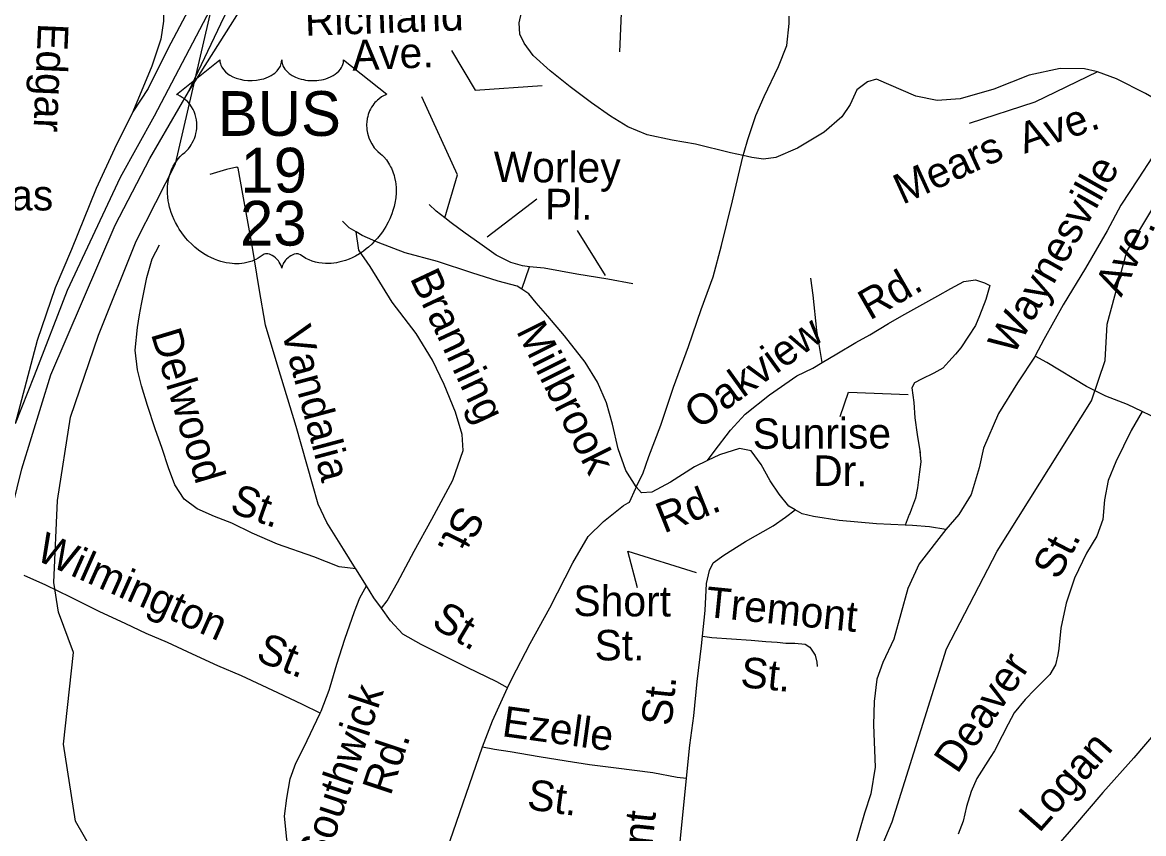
# Model space of a CAD drawing. Extents: x 925297 to 940193, y 663541 to 689899.
# Drawn here: x 929116 to 929667, y 688331 to 688730 of the extents above; entities that cross this region are included whole.
import ezdxf

# ---------------------------------------------------------------- set-up
doc = ezdxf.new("R2010")
doc.units = 0
doc.layers.add('Default', color=7, linetype='Continuous')

msp = doc.modelspace()

# ---------------------------------------------------------------- linework, layer by layer
at = {"layer": 'Default'}
for p, q in [((929412.85, 688786.82), (929409.51, 688715.72)), ((929361.53, 688598.93), (929365.32, 688610.03)), ((929285.25, 688453.07), (929279.96, 688461.55))]:
    msp.add_line(p, q, dxfattribs=at)
for points in [[(929131.57, 688454.71), (929133.41, 688495.05), (929139.69, 688536.07), (929153.55, 688576.4), (929172.02, 688622.58), (929191.38, 688660.69), (929209.61, 688739.05), (929203.87, 688824.44)], [(929119.59, 688819.56), (929137.45, 688811.52), (929149.65, 688804.67), (929161.85, 688794.84), (929172.86, 688781.14), (929179.71, 688767.74), (929183.88, 688754.04), (929185.36, 688742.13), (929185.46, 688730.85), (929184.09, 688721.85), (929179.67, 688708.57), (929170.37, 688686.19)], [(929197.77, 688696.08), (929242.19, 688766.42), (929266.51, 688806.41)], [(929197.77, 688696.08), (929215.22, 688732.92), (929232.57, 688767.49), (929244.99, 688790.68), (929250.18, 688801.15)], [(929240.68, 688799), (929227.23, 688772.53), (929180.84, 688684.11), (929164.1, 688653.95), (929138.06, 688598.39), (929121.88, 688556.31), (929112.47, 688532.84)], [(929229.97, 688797.34), (929209.05, 688757.78), (929187.54, 688717.1), (929177.86, 688697.73), (929170.37, 688686.19)], [(929470.4, 688664.68), (929464.09, 688665.96), (929446.9, 688670.3), (929435.45, 688672.32), (929423.18, 688674.85), (929413.65, 688678.87), (929405.08, 688684.08), (929395.85, 688690.64), (929385.4, 688698.5), (929375.45, 688706.3), (929367.11, 688713.88), (929362.78, 688719.95), (929360.52, 688724.43), (929360.24, 688729.89), (929361.44, 688735.06)], [(929470.4, 688664.68), (929470.79, 688666.32), (929472.7, 688672.6), (929476.64, 688684.36), (929480.67, 688693.76), (929487.77, 688708.46), (929491.81, 688718.81), (929493, 688729.64), (929492.92, 688733.26)], [(929326.96, 688716.39), (929338.7, 688696.82), (929371.57, 688699.16)], [(929644.42, 688705.84), (929643.92, 688706.02), (929638.16, 688707.3), (929626.13, 688707.45), (929610.84, 688704.16), (929593.61, 688697.37), (929577.08, 688692.65), (929565.66, 688691.83), (929555.16, 688693.9), (929535.94, 688702.2), (929531.38, 688701.01), (929526.27, 688697.05), (929522.96, 688689.76), (929518.86, 688683.7), (929510.22, 688676.2), (929497.09, 688668.28), (929486.34, 688663.71), (929480.42, 688663), (929474.68, 688663.81), (929470.4, 688664.68)], [(929644.42, 688705.84), (929613.77, 688690.97), (929581.49, 688680.44)], [(929687.72, 688685.27), (929677.43, 688689.85), (929668.13, 688695.21), (929653.77, 688702.41), (929644.42, 688705.84)], [(929096.73, 688257.47), (929094.63, 688345.9), (929098.42, 688411.96), (929101.91, 688442.91), (929106.59, 688473.2), (929115.78, 688510.69), (929130.1, 688556.83), (929161.64, 688630.45), (929178.69, 688663.27), (929197.77, 688696.08)], [(929323.72, 688634.01), (929329.89, 688655.25), (929312.41, 688693.56)], [(929170.37, 688686.19), (929161.35, 688668.03), (929152.39, 688648.51), (929140.25, 688618.43), (929132.28, 688599.71), (929123.36, 688573.77), (929112.47, 688532.84)], [(929687.72, 688685.27), (929685.16, 688682.24), (929678.13, 688673.12), (929671.52, 688664.02), (929664.47, 688653.24), (929655.97, 688640.24), (929649.18, 688627.76), (929638.6, 688609.34), (929627.68, 688591.29), (929618.14, 688574.27), (929613.88, 688566.19), (929613.79, 688566.05)], [(929417.81, 688501.72), (929420.99, 688508.22), (929424.02, 688516.71), (929429.89, 688532.15), (929436.16, 688550.79), (929443.43, 688570.82), (929449.75, 688588.94), (929455.61, 688605.02), (929459.63, 688620.42), (929465.18, 688642.36), (929468.77, 688657.85), (929470.4, 688664.68)], [(929279.96, 688461.55), (929279.86, 688461.72), (929273.89, 688471.17), (929265.74, 688484.32), (929261.49, 688493.31), (929258.62, 688503.08), (929250.59, 688531.48), (929241.75, 688560.52), (929235.57, 688581.25), (929232.46, 688599.32), (929228.98, 688620.54), (929224.47, 688645.77), (929222.17, 688658.48), (929221.5, 688659.06), (929216.34, 688657.91), (929208.2, 688655.3)], [(929414.97, 688208.79), (929433.96, 688225.32), (929496.81, 688258.69), (929509.21, 688269.84), (929523.98, 688290.52), (929543.64, 688337.07), (929570.32, 688422.17), (929595.25, 688470.11), (929641.53, 688544.1), (929648.24, 688563.88), (929649.28, 688581.85), (929658.96, 688617.52), (929685.35, 688661.41)], [(929369, 688643.32), (929344.55, 688624.55)], [(929323.72, 688634.01), (929319.48, 688637.36), (929316.07, 688640.59)], [(929280.09, 688627.12), (929276.73, 688629.2), (929273.36, 688632.4)], [(929365.32, 688610.03), (929361.83, 688610.4), (929356.13, 688612.19), (929349, 688615.79), (929341, 688621.37), (929333.65, 688626.53), (929326.82, 688631.56), (929323.72, 688634.01)], [(929361.53, 688598.93), (929359.3, 688600.42), (929349.98, 688602.91), (929337.02, 688607.04), (929320.17, 688612.54), (929304.27, 688616.88), (929290.99, 688621.87), (929283.02, 688625.32), (929280.09, 688627.12)], [(929292.56, 688442.09), (929295.44, 688445.81), (929300.4, 688454.69), (929308.58, 688470.21), (929317.26, 688485.87), (929327.69, 688505.02), (929332.66, 688519.6), (929332.29, 688527.48), (929328.95, 688538.55), (929323.47, 688552.09), (929317.63, 688564.09), (929309.62, 688577.16), (929297.83, 688592.68), (929287.04, 688610.1), (929281.44, 688618.21), (929280.09, 688627.12)], [(929388.76, 688627.91), (929402.5, 688605.78)], [(929279.96, 688461.55), (929271.72, 688462.45), (929259.33, 688467.4), (929241.52, 688473.63), (929229.09, 688479.09), (929218.95, 688483.89), (929210.49, 688487.26), (929201.98, 688490.95), (929195.66, 688495.7), (929191.06, 688502.73), (929187.89, 688511.22), (929184.85, 688520.69), (929181.43, 688530.37), (929177.6, 688541.84), (929174.66, 688551.54), (929172.63, 688559.38), (929171.44, 688568.95), (929172.72, 688580.17), (929173.59, 688586.42), (929174.63, 688591.55), (929177.3, 688604.8), (929179.9, 688613.97), (929183.53, 688620.77)], [(929416.17, 688601.65), (929403.91, 688603.85), (929388.54, 688606.37), (929372.59, 688609.25), (929365.32, 688610.03)], [(929509.25, 688562.97), (929506.61, 688578.74), (929504.83, 688596.05), (929503.55, 688604.45)], [(929509.25, 688562.97), (929516.4, 688567.28), (929525.74, 688572.7), (929532.66, 688576.62), (929541.71, 688582.15), (929548.34, 688585.84), (929557.1, 688590.74), (929566.1, 688595.7), (929572.44, 688599.39), (929578.84, 688602.74), (929584.6, 688603.6), (929588.93, 688602.1), (929591.52, 688600.72), (929589.56, 688593.86), (929586.56, 688585.9), (929584.6, 688581.12), (929581.09, 688575.87), (929577.28, 688570.16), (929574.69, 688566.99), (929571.46, 688563.47), (929568.52, 688560.19), (929564.02, 688557.71), (929557.97, 688554.77), (929554.51, 688552.98), (929553.3, 688550.44), (929554.22, 688543.3), (929554.68, 688535.69), (929555.87, 688527.51), (929557.3, 688518.54)], [(929417.81, 688501.72), (929412.65, 688509.75), (929408.95, 688520.43), (929406.2, 688532.63), (929403.17, 688543.07), (929398.68, 688553.26), (929392.75, 688563.16), (929382.57, 688576.08), (929374.32, 688585.75), (929368.67, 688592.22), (929364.95, 688596.66), (929361.53, 688598.93)], [(929710.63, 688577.91), (929705.21, 688574.01), (929704.05, 688569.73), (929703.18, 688567.39), (929702.12, 688561.22), (929701.47, 688551.86), (929701.2, 688544.95), (929699.85, 688537.99), (929697.02, 688533), (929692.95, 688530.38), (929690.07, 688529.68), (929684.68, 688530.96), (929670.61, 688536.91), (929666.37, 688538.89)], [(929613.79, 688566.05), (929605.22, 688552.88), (929595.8, 688537.84), (929588.39, 688520.79), (929586.33, 688511.1), (929582.47, 688498.07), (929576.32, 688488.2), (929569.95, 688480.77)], [(929666.37, 688538.89), (929659.17, 688542.25), (929648.52, 688546.46), (929642.42, 688549.43), (929639.03, 688551.14), (929619.6, 688562.86), (929613.79, 688566.05)], [(929452.76, 688514.7), (929456.1, 688519.25), (929464.11, 688529.63), (929471.32, 688537.47), (929483.25, 688547.04), (929496.74, 688556.44), (929504.64, 688560.19), (929509.25, 688562.97)], [(929518.08, 688536.44), (929522.15, 688548.3), (929551.41, 688547.19)], [(929666.37, 688538.89), (929664.59, 688535.79), (929661.1, 688529.49), (929653.45, 688514.11), (929649.76, 688504.98), (929647.96, 688495.33), (929647.11, 688485.73), (929644.19, 688477.54), (929639.1, 688469.26), (929633.2, 688456.92), (929629.11, 688444.61), (929626.53, 688432.27), (929625.49, 688422.38), (929624.93, 688419.12), (929623.82, 688414.32), (929621.13, 688409.47), (929613.73, 688402.17), (929608.93, 688397.18), (929603.53, 688390.7), (929600.53, 688385.13), (929597.58, 688379.36), (929593.88, 688371.99), (929591.81, 688368.76), (929585.26, 688358.43), (929582.38, 688352.04), (929580.05, 688344.62), (929578.53, 688337.4), (929576.09, 688330.94)], [(929495.92, 688490.52), (929492.78, 688492.36), (929488.09, 688498.2), (929483.6, 688504.7), (929479.27, 688512.78), (929474.24, 688519.47), (929468.59, 688520.69), (929458.79, 688517.58), (929452.76, 688514.7)], [(929452.76, 688514.7), (929446.37, 688511.65), (929434.63, 688504.06), (929425.52, 688499.25), (929420.44, 688498.83), (929417.81, 688501.72)], [(929557.25, 688519.18), (929557.63, 688514.15), (929557.04, 688509.16), (929556.1, 688501.34), (929555.06, 688496.18), (929553.15, 688490.98), (929552.18, 688488.68), (929551.97, 688488.25), (929549.95, 688482.91)], [(929354.58, 688402.95), (929356.58, 688407.37), (929365.69, 688424.83), (929375.31, 688442.35), (929386.66, 688464.38), (929394.11, 688477.44), (929401.65, 688484.83), (929411.47, 688492.68), (929413.88, 688493.96), (929414.43, 688494.25), (929417.55, 688501.19), (929417.69, 688501.49), (929417.81, 688501.72)], [(929450.3, 688428.32), (929451.64, 688441.05), (929452.38, 688454.2), (929453.77, 688460.68), (929455.6, 688464.44), (929460.87, 688468.14), (929471.57, 688474.92), (929485.12, 688482.69), (929491.09, 688486.89), (929495.92, 688490.52)], [(929549.95, 688482.91), (929535.87, 688483.56), (929517.54, 688485.21), (929504.95, 688487.19), (929499.28, 688488.56), (929495.92, 688490.52)], [(929766.17, 688488.37), (929749.41, 688469.03), (929736.3, 688453.99), (929719.22, 688434.65), (929705.47, 688418.91), (929694.03, 688405.79), (929678.59, 688387.54), (929662.33, 688368.55), (929647.17, 688351.55), (929632.64, 688334.68), (929585.17, 688279.86), (929560.06, 688251.62), (929555.97, 688248.14)], [(929569.95, 688480.77), (929561.91, 688482.17), (929553.54, 688482.75), (929549.95, 688482.91)], [(929569.95, 688480.77), (929556.84, 688463.98), (929551.28, 688451.83), (929544.4, 688426.93), (929539.03, 688415.4), (929536.07, 688407.26), (929534.72, 688396.19), (929534.36, 688384.82), (929535.15, 688363.97), (929533.06, 688350.8), (929530, 688341.4), (929525.01, 688324.27), (929522.12, 688308.28), (929520.15, 688299.54), (929518.92, 688295.07), (929517.81, 688291.34), (929515.7, 688286.89)], [(929418.44, 688452.18), (929413.63, 688470.1), (929447.28, 688459.61)], [(929262.46, 688390.52), (929253.71, 688394.76), (929241.67, 688400.48), (929223.71, 688408.84), (929212.2, 688413.86), (929199.73, 688419.52), (929187.37, 688425.22), (929177, 688429.72), (929166.98, 688434.5), (929153.85, 688440.52), (929139.73, 688447.55), (929127.65, 688453.46), (929117.01, 688458.25)], [(929194.44, 688231.89), (929190.85, 688243.23), (929176.68, 688272.55), (929165.3, 688290.18), (929154.23, 688316.6), (929142.17, 688337.44), (929136.32, 688375.28), (929141.14, 688420.33), (929133.86, 688440.2), (929131.57, 688454.71)], [(929262.46, 688390.52), (929262.94, 688391.47), (929266.93, 688401.82), (929267.43, 688403.48), (929270.65, 688414.6), (929274.59, 688426.91), (929279.38, 688440.44), (929281.86, 688447.14), (929285.25, 688453.07)], [(929292.56, 688442.09), (929288.89, 688447.24), (929285.25, 688453.07)], [(929354.58, 688402.95), (929349.28, 688405.86), (929334.62, 688412.93), (929312.1, 688424.24), (929303.09, 688429.28), (929296.95, 688435.94), (929292.56, 688442.09)], [(929442.45, 688358.53), (929442.45, 688358.54), (929444.16, 688374.72), (929446.02, 688389.22), (929447.69, 688406.12), (929449.8, 688423.55), (929450.3, 688428.32)], [(929450.3, 688428.32), (929454.92, 688427.76), (929464.63, 688427.13), (929474.31, 688426.39), (929481.44, 688425.75), (929486.99, 688425.44), (929491.26, 688424.94), (929495.72, 688424.88), (929500.8, 688424.36), (929503.05, 688422.91), (929505.77, 688418.96), (929506.6, 688415.65), (929506.73, 688413.52)], [(929342.29, 688373.99), (929347.18, 688386.67), (929354.58, 688402.95)], [(929247.8, 688318.49), (929246.08, 688328.54), (929244.96, 688339.91), (929246.01, 688348.65), (929247.65, 688358.24), (929250.45, 688365.96), (929254.48, 688373.57), (929262.46, 688390.52)], [(929311.84, 688288.64), (929314.89, 688297.18), (929324.67, 688323.22), (929342.29, 688373.99)], [(929342.29, 688373.99), (929348.18, 688372.88), (929355.81, 688371.74), (929370.14, 688369.17), (929383.4, 688367.11), (929394.76, 688365.34), (929407.92, 688363.57), (929425.99, 688361.3), (929437.83, 688359.07), (929442.45, 688358.53)], [(929433.62, 688261.73), (929433.04, 688262.72), (929433, 688263.64), (929432.94, 688265.12), (929434.42, 688280.53), (929436.14, 688296.47), (929437.61, 688310.56), (929439.12, 688323.75), (929440.07, 688333.96), (929440.99, 688343.63), (929442.45, 688358.53)]]:
    msp.add_lwpolyline(points, dxfattribs=at)
msp.add_lwpolyline([(929213.15, 688711.69), (929213.21, 688710.8), (929213.42, 688709.76), (929213.58, 688709.22), (929214.07, 688708.19), (929214.88, 688706.97), (929216, 688705.78), (929217.27, 688704.74), (929218.12, 688704.19), (929219.57, 688703.41), (929221.22, 688702.72), (929223.05, 688702.19), (929224.92, 688701.81), (929226.96, 688701.59), (929228.99, 688701.55), (929231.17, 688701.71), (929233.58, 688702.18), (929234.7, 688702.47), (929235.94, 688702.89), (929237.1, 688703.37), (929238.36, 688704.05), (929239.38, 688704.7), (929240.18, 688705.28), (929241.31, 688706.36), (929242.2, 688707.48), (929242.58, 688708.1), (929242.91, 688708.71), (929243.35, 688709.99), (929243.48, 688710.55), (929243.57, 688711.73), (929243.64, 688710.74), (929243.74, 688710.13), (929243.91, 688709.52), (929244.16, 688708.88), (929244.61, 688707.98), (929245.11, 688707.23), (929246.06, 688706.11), (929246.65, 688705.55), (929247.19, 688705.12), (929248.63, 688704.12), (929250.32, 688703.27), (929251.15, 688702.9), (929252, 688702.6), (929253.08, 688702.28), (929254.2, 688702.01), (929255.3, 688701.82), (929256.43, 688701.66), (929257.59, 688701.57), (929258.53, 688701.55), (929259.69, 688701.56), (929260.75, 688701.62), (929261.84, 688701.75), (929263.05, 688701.95), (929264.02, 688702.16), (929265.3, 688702.5), (929266.45, 688702.92), (929267.47, 688703.36), (929268.79, 688704.05), (929269.85, 688704.71), (929270.63, 688705.34), (929271.56, 688706.2), (929272.44, 688707.21), (929272.95, 688707.95), (929273.32, 688708.72), (929273.66, 688709.52), (929273.86, 688710.38), (929273.97, 688711.12), (929273.99, 688711.75), (929295.24, 688694.82), (929294.74, 688694.63), (929293.59, 688694.06), (929292.67, 688693.52), (929291.21, 688692.49), (929290.58, 688691.93), (929289.95, 688691.34), (929289.37, 688690.71), (929288.87, 688690.12), (929288.25, 688689.26), (929287.7, 688688.41), (929287.16, 688687.47), (929286.76, 688686.65), (929286.11, 688684.94), (929285.8, 688683.86), (929285.6, 688682.95), (929285.34, 688681.05), (929285.28, 688680.15), (929285.28, 688679.25), (929285.33, 688678.31), (929285.42, 688677.41), (929285.58, 688676.47), (929285.73, 688675.64), (929286, 688674.62), (929286.37, 688673.44), (929286.84, 688672.3), (929287.81, 688670.45), (929289.06, 688668.57), (929289.95, 688667.51), (929290.83, 688666.61), (929292.14, 688665.5), (929292.85, 688664.87), (929293.67, 688664.06), (929295, 688662.51), (929295.54, 688661.78), (929296.08, 688660.97), (929296.59, 688660.13), (929297.09, 688659.22), (929297.49, 688658.43), (929298.24, 688656.61), (929298.78, 688654.84), (929299.03, 688653.91), (929299.43, 688651.82), (929299.58, 688650.79), (929299.74, 688648.76), (929299.75, 688646.3), (929299.56, 688643.96), (929299.12, 688641.24), (929298.76, 688639.6), (929298.2, 688637.71), (929297.66, 688636.06), (929296.69, 688633.64), (929295.83, 688631.88), (929294.71, 688629.82), (929293.94, 688628.58), (929293.05, 688627.24), (929291.93, 688625.71), (929290.63, 688624.08), (929289.06, 688622.36), (929287.79, 688621.09), (929286.13, 688619.61), (929285.13, 688618.78), (929283.7, 688617.7), (929281.74, 688616.39), (929279.81, 688615.27), (929278.16, 688614.43), (929276.71, 688613.81), (929274.82, 688613.09), (929271.69, 688612.22), (929270.54, 688611.98), (929269.19, 688611.78), (929267.92, 688611.66), (929266.69, 688611.58), (929265.03, 688611.58), (929263.39, 688611.71), (929261.83, 688611.93), (929260.21, 688612.27), (929258.52, 688612.78), (929256.98, 688613.38), (929255.42, 688614.14), (929252.79, 688615.8), (929252.03, 688616.2), (929251.61, 688616.32), (929250.59, 688616.37), (929249.64, 688616.17), (929248.66, 688615.78), (929248.07, 688615.46), (929247.28, 688614.95), (929246.68, 688614.47), (929245.95, 688613.78), (929245.45, 688613.2), (929245.07, 688612.75), (929244.33, 688611.58), (929244.06, 688611.03), (929243.79, 688610.31), (929243.54, 688609.26), (929243.21, 688610.59), (929242.82, 688611.47), (929242.37, 688612.22), (929241.9, 688612.89), (929241.16, 688613.74), (929240.49, 688614.38), (929239.69, 688615.04), (929238.83, 688615.55), (929238.15, 688615.9), (929237.52, 688616.14), (929236.76, 688616.33), (929236.13, 688616.38), (929235.61, 688616.37), (929234.91, 688616.21), (929233.94, 688615.51), (929233.03, 688614.88), (929232.04, 688614.27), (929230.86, 688613.64), (929230, 688613.24), (929228.97, 688612.84), (929227.76, 688612.44), (929226.46, 688612.1), (929225.11, 688611.83), (929223.93, 688611.64), (929222.67, 688611.53), (929221.52, 688611.49), (929220.33, 688611.51), (929219.21, 688611.59), (929217.92, 688611.71), (929216.31, 688611.95), (929214.98, 688612.25), (929213.58, 688612.62), (929212.13, 688613.08), (929210.59, 688613.67), (929208.66, 688614.51), (929207.31, 688615.2), (929205.19, 688616.42), (929202.71, 688618.14), (929200.83, 688619.66), (929199.46, 688620.9), (929197.43, 688622.96), (929196.25, 688624.31), (929194.38, 688626.72), (929193.19, 688628.46), (929192.42, 688629.74), (929191.29, 688631.8), (929190.67, 688633.1), (929189.86, 688634.98), (929189.23, 688636.7), (929188.7, 688638.33), (929188.42, 688639.38), (929188.02, 688641.2), (929187.77, 688642.49), (929187.54, 688644.26), (929187.4, 688646.13), (929187.38, 688647.85), (929187.42, 688649.29), (929187.59, 688650.96), (929187.87, 688652.73), (929188.21, 688654.25), (929188.52, 688655.34), (929188.97, 688656.67), (929189.56, 688658.14), (929190.27, 688659.55), (929190.94, 688660.72), (929191.78, 688661.97), (929192.61, 688663.04), (929193.69, 688664.22), (929194.82, 688665.3), (929195.86, 688666.14), (929197.09, 688667.35), (929197.73, 688668.08), (929198.5, 688669.09), (929199.12, 688670.03), (929199.61, 688670.88), (929200.25, 688672.12), (929200.64, 688673.05), (929201.13, 688674.48), (929201.38, 688675.49), (929201.63, 688676.78), (929201.79, 688678), (929201.85, 688679.52), (929201.82, 688680.77), (929201.65, 688682.24), (929201.38, 688683.65), (929201.04, 688684.88), (929200.52, 688686.29), (929200.03, 688687.32), (929199.22, 688688.71), (929198.31, 688690.01), (929197.38, 688691.06), (929196.44, 688692), (929195.53, 688692.71), (929194.67, 688693.32), (929193.59, 688693.97), (929192.55, 688694.49), (929191.9, 688694.75)], close=True, dxfattribs=at)

# ---------------------------------------------------------------- texts
for s, rotation, p in [('Richland', 2.0451, (929255.15, 688723.54)), ('Edgar', 267.5236, (929123.85, 688730.01)), ('Ave.', 2.5221, (929278.37, 688706.43)), ('Ave.', 18.7021, (929608.58, 688665.52)), ('Mears', 24.5256, (929548.66, 688640.4)), ('Worley', 359.6528, (929347.69, 688651.69)), ('Waynesville', 60.5598, (929603.07, 688565.84)), ('Texas', 359.642, (929076.61, 688638.02)), ('Pl.', 359.3622, (929372.86, 688633.41)), ('Ave.', 64.3653, (929656.2, 688594.71)), ('Branning', 295.2103, (929306.3, 688604.5)), ('Rd.', 29.8644, (929532.55, 688583.46)), ('Vandalia', 284.9973, (929243.15, 688578.8)), ('Millbrook', 296.7454, (929358.58, 688578.45)), ('Oakview', 35.7626, (929448.47, 688529.65)), ('Delwood', 286.7509, (929179.15, 688577.08)), ('Sunrise', 0.1659, (929475.04, 688520.47)), ('Dr.', 359.6338, (929504.7, 688502.27)), ('St.', 340.4796, (929217.42, 688489.57)), ('Rd.', 21.8991, (929431.37, 688478.77)), ('St.', 243.1819, (929330.56, 688493.49)), ('Wilmington', 335.9898, (929121.89, 688466.18)), ('St.', 62.4756, (929625.28, 688455.48)), ('Short', 359.699, (929386.9, 688438.28)), ('Tremont', 354.2592, (929451.44, 688437.9)), ('St.', 329.0029, (929316.47, 688433.49)), ('St.', 359.8975, (929397.3, 688416.46)), ('St.', 338.1584, (929230.28, 688416.63)), ('St.', 354.2592, (929468.63, 688403.4)), ('Deaver', 55.895, (929575.58, 688360.21)), ('Southwick', 71.4369, (929264.77, 688314.76)), ('St.', 84.1086, (929435.06, 688383.87)), ('Ezelle', 352.1496, (929351.37, 688379.25)), ('Rd.', 71.4721, (929297.02, 688349.46)), ('Logan', 48.5899, (929615.82, 688331.23)), ('St.', 352.1496, (929363.69, 688343.34)), ('Trenmont', 83.9555, (929418.43, 688256.33))]:
    msp.add_text(s, height=15, rotation=rotation, dxfattribs=at).set_placement(p)
for s, p in [('BUS', (929212.17, 688674.37)), ('19', (929223.26, 688646.51)), ('23', (929223.04, 688620.42))]:
    msp.add_text(s, height=22, dxfattribs=at).set_placement(p)

doc.saveas('drawing.dxf')
